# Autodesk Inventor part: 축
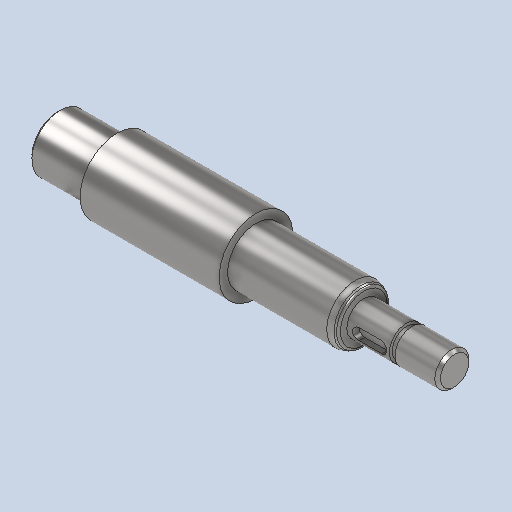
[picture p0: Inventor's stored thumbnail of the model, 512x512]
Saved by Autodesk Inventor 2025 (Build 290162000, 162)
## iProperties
Created: 2024-08
Part Number: 축
Material: 강철, 연강
Document SubType Name: Modeling
Designer: Administrator
Density: 7.86 g/cm^3
Appearance: 기본값
Author: jhkim
Sending System: Autodesk Inventor 2025
Preprocessor: ST-DEVELOPER v20
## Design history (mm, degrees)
feature "솔리드2"
node "솔리드1"
